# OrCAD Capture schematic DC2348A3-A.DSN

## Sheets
1 PAGE3: size B; title: HIGH POWER POLY-PHASE; rev: 3; company: TM; note: BI-DIRECTIONAL SUPPLY/CHARGER
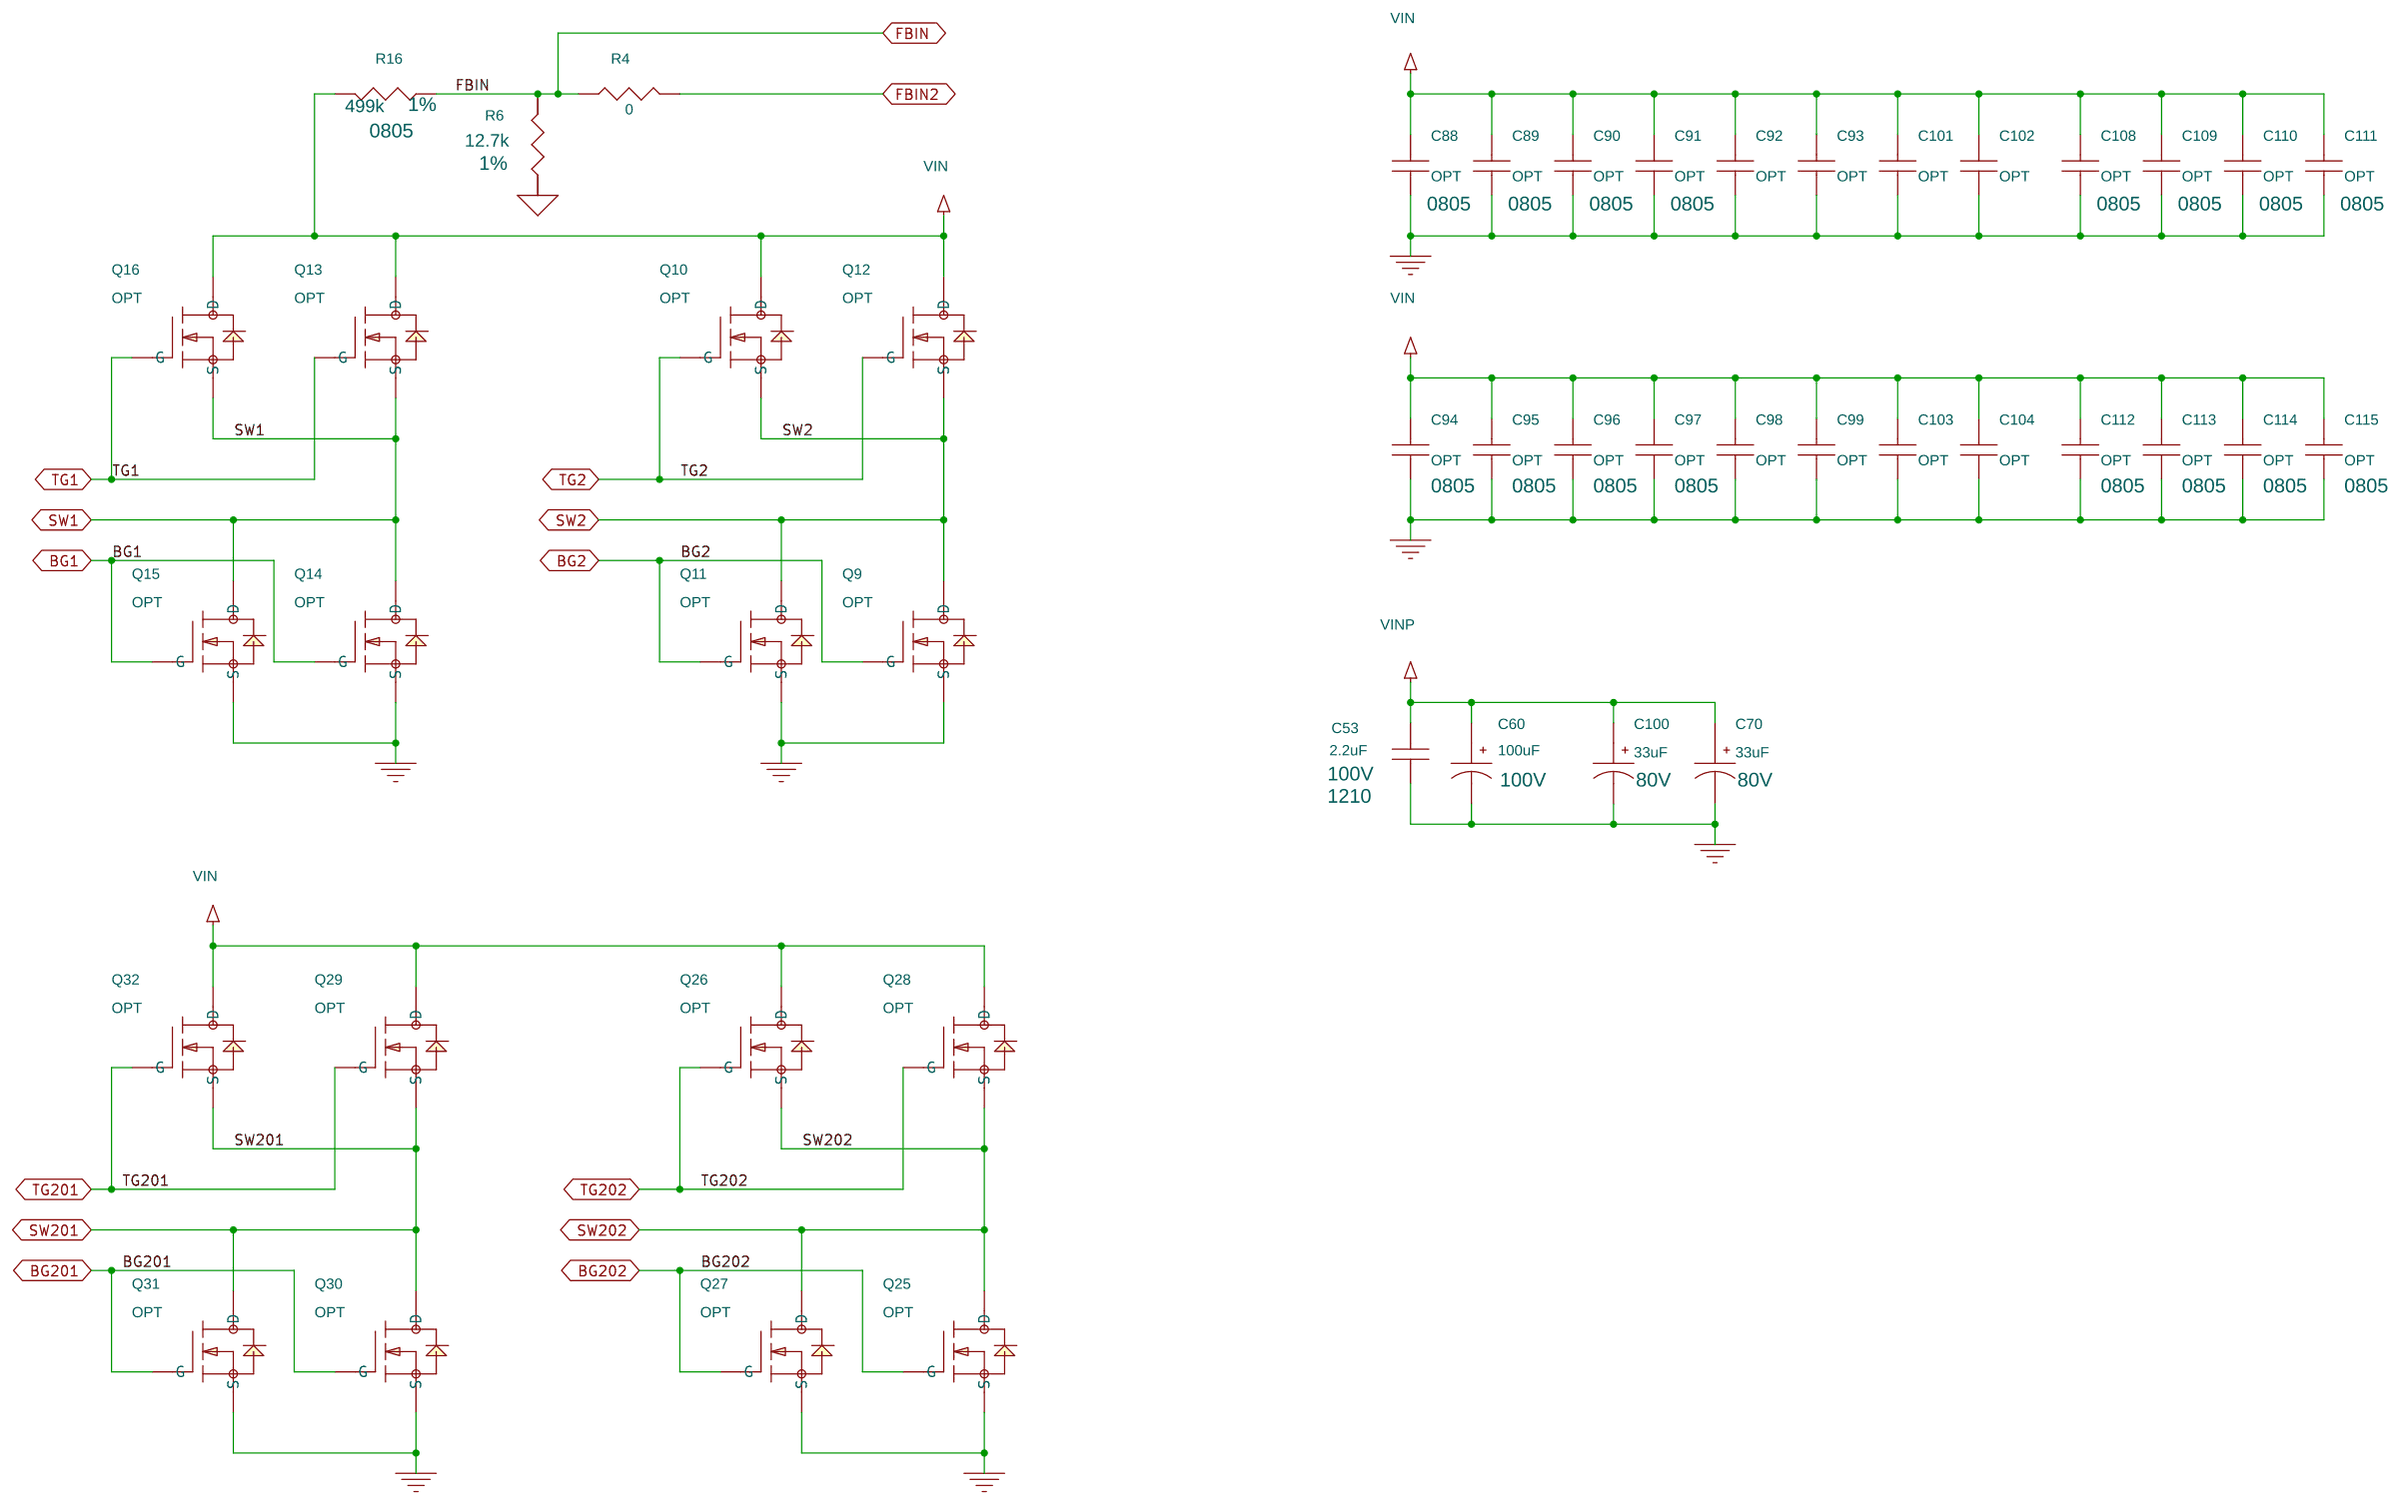
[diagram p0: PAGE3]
2 PAGE1: size Custom
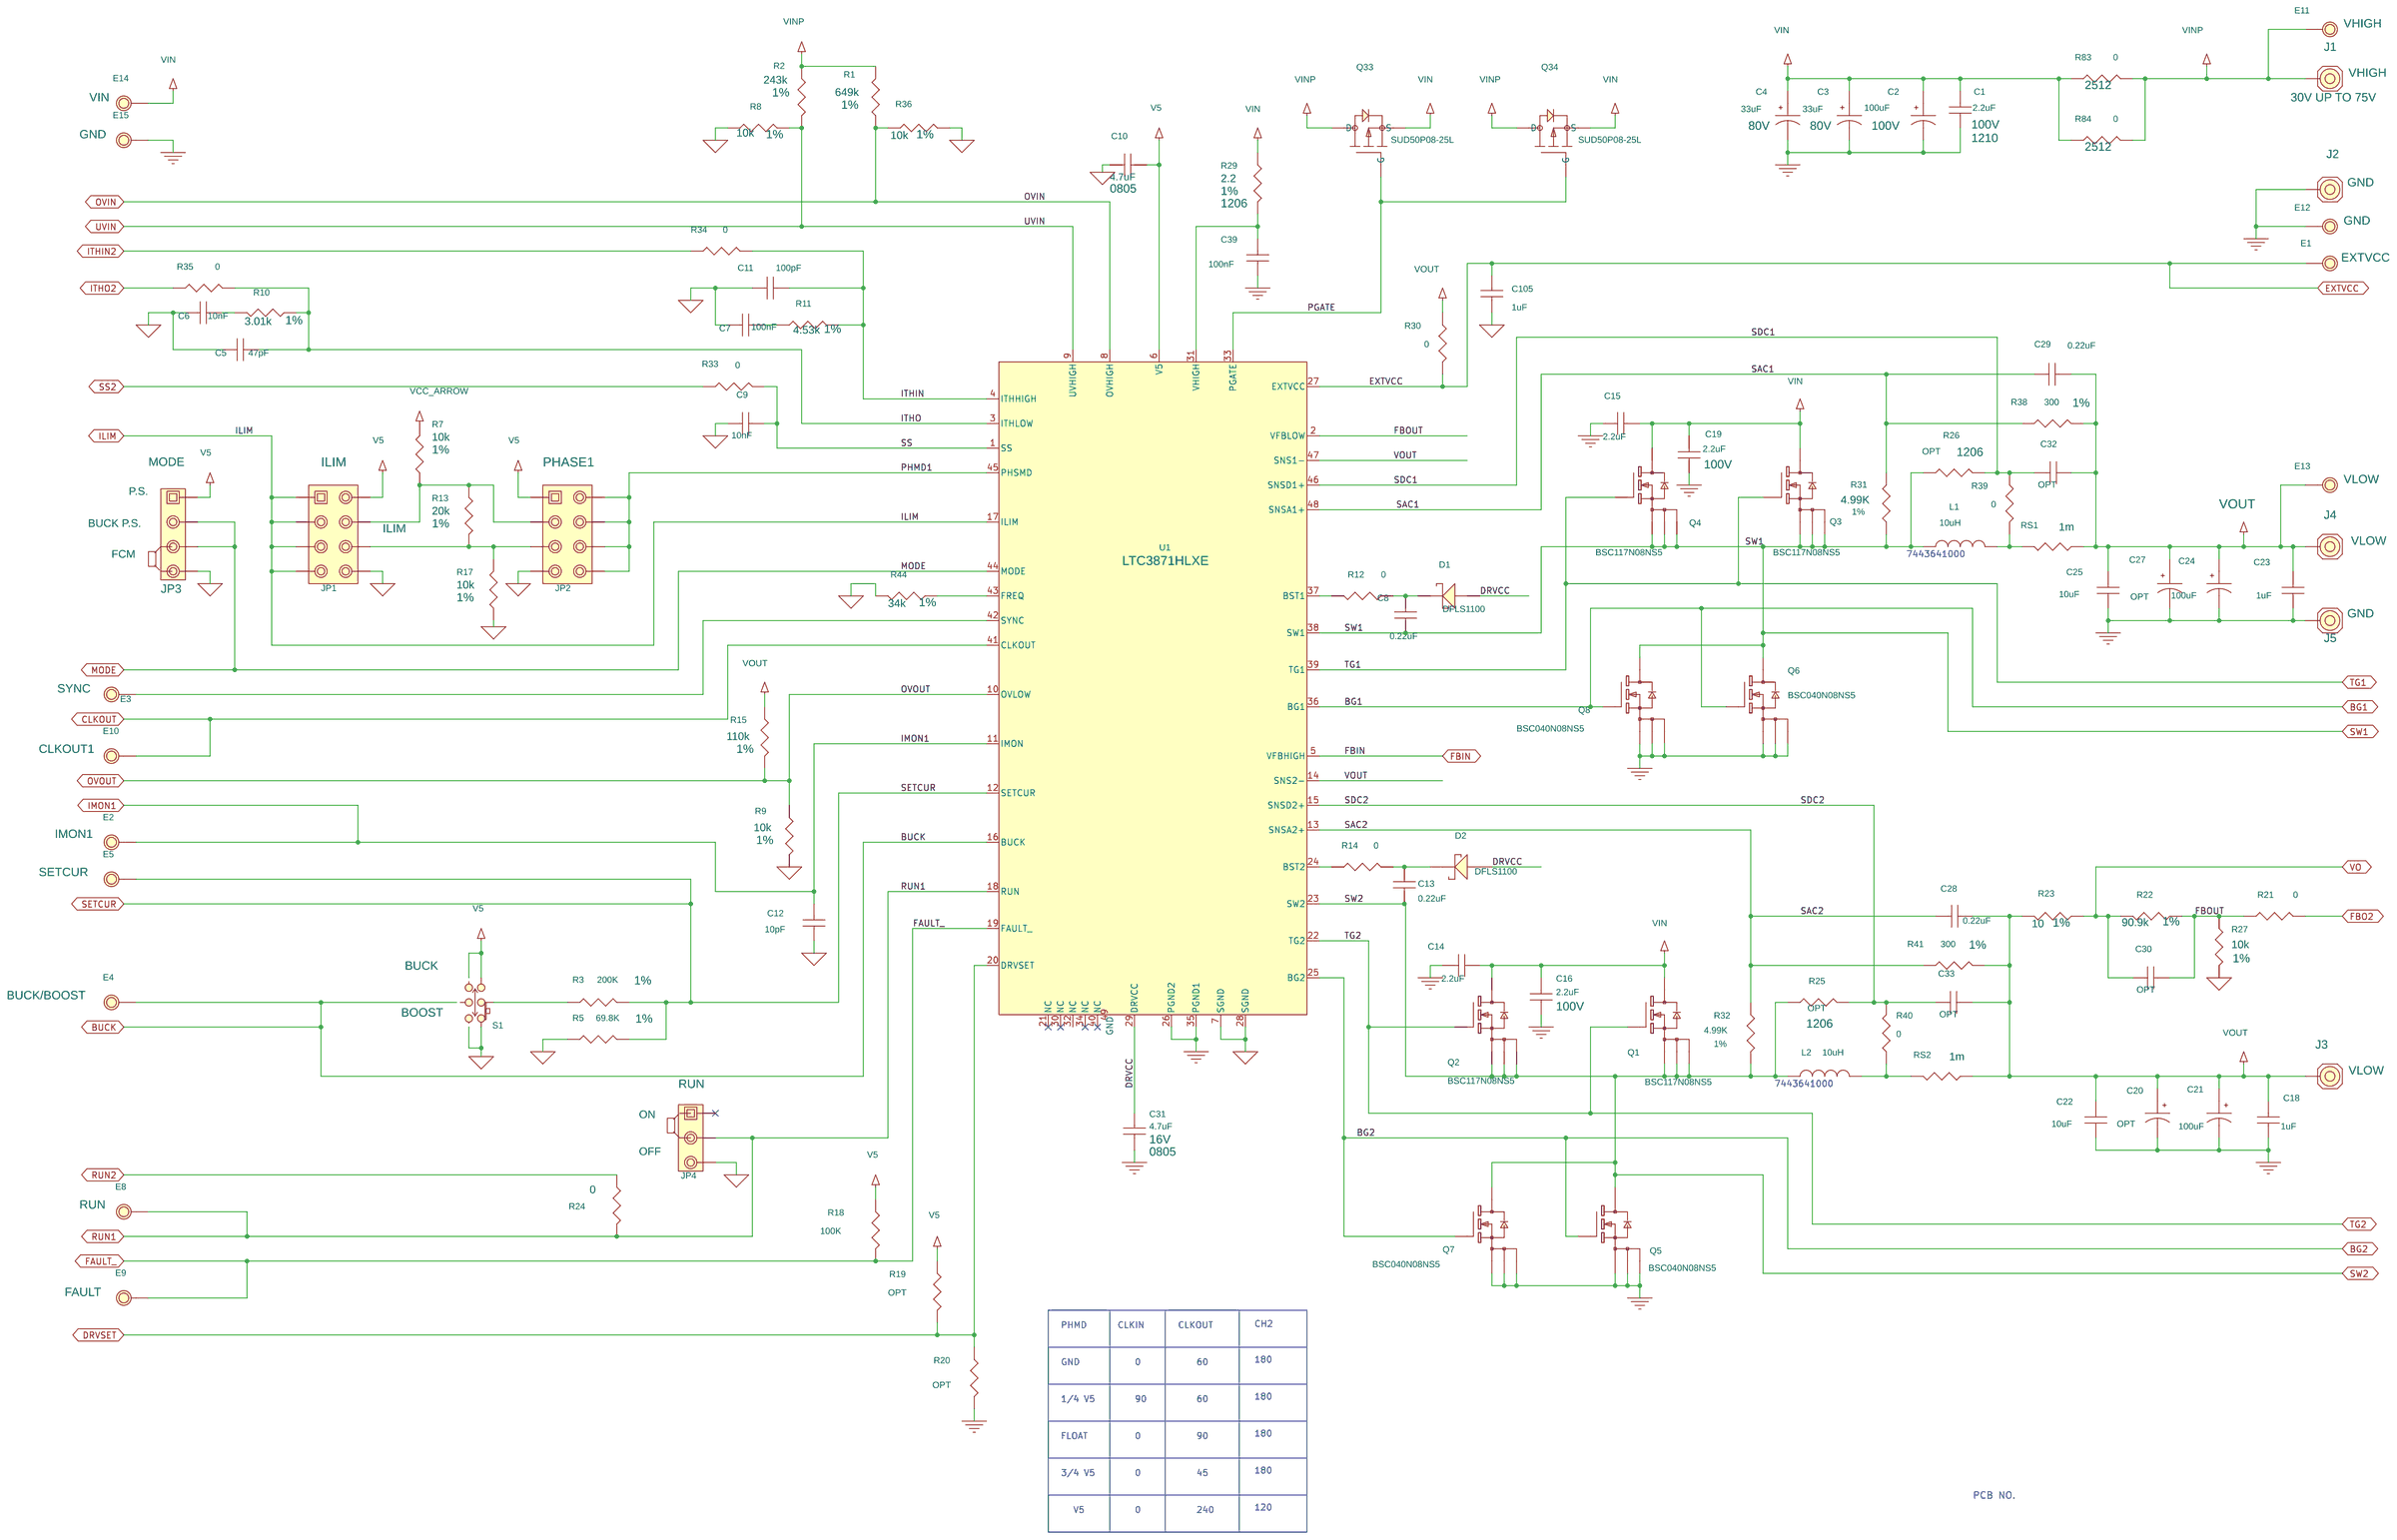
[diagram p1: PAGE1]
3 PAGE2: size Custom
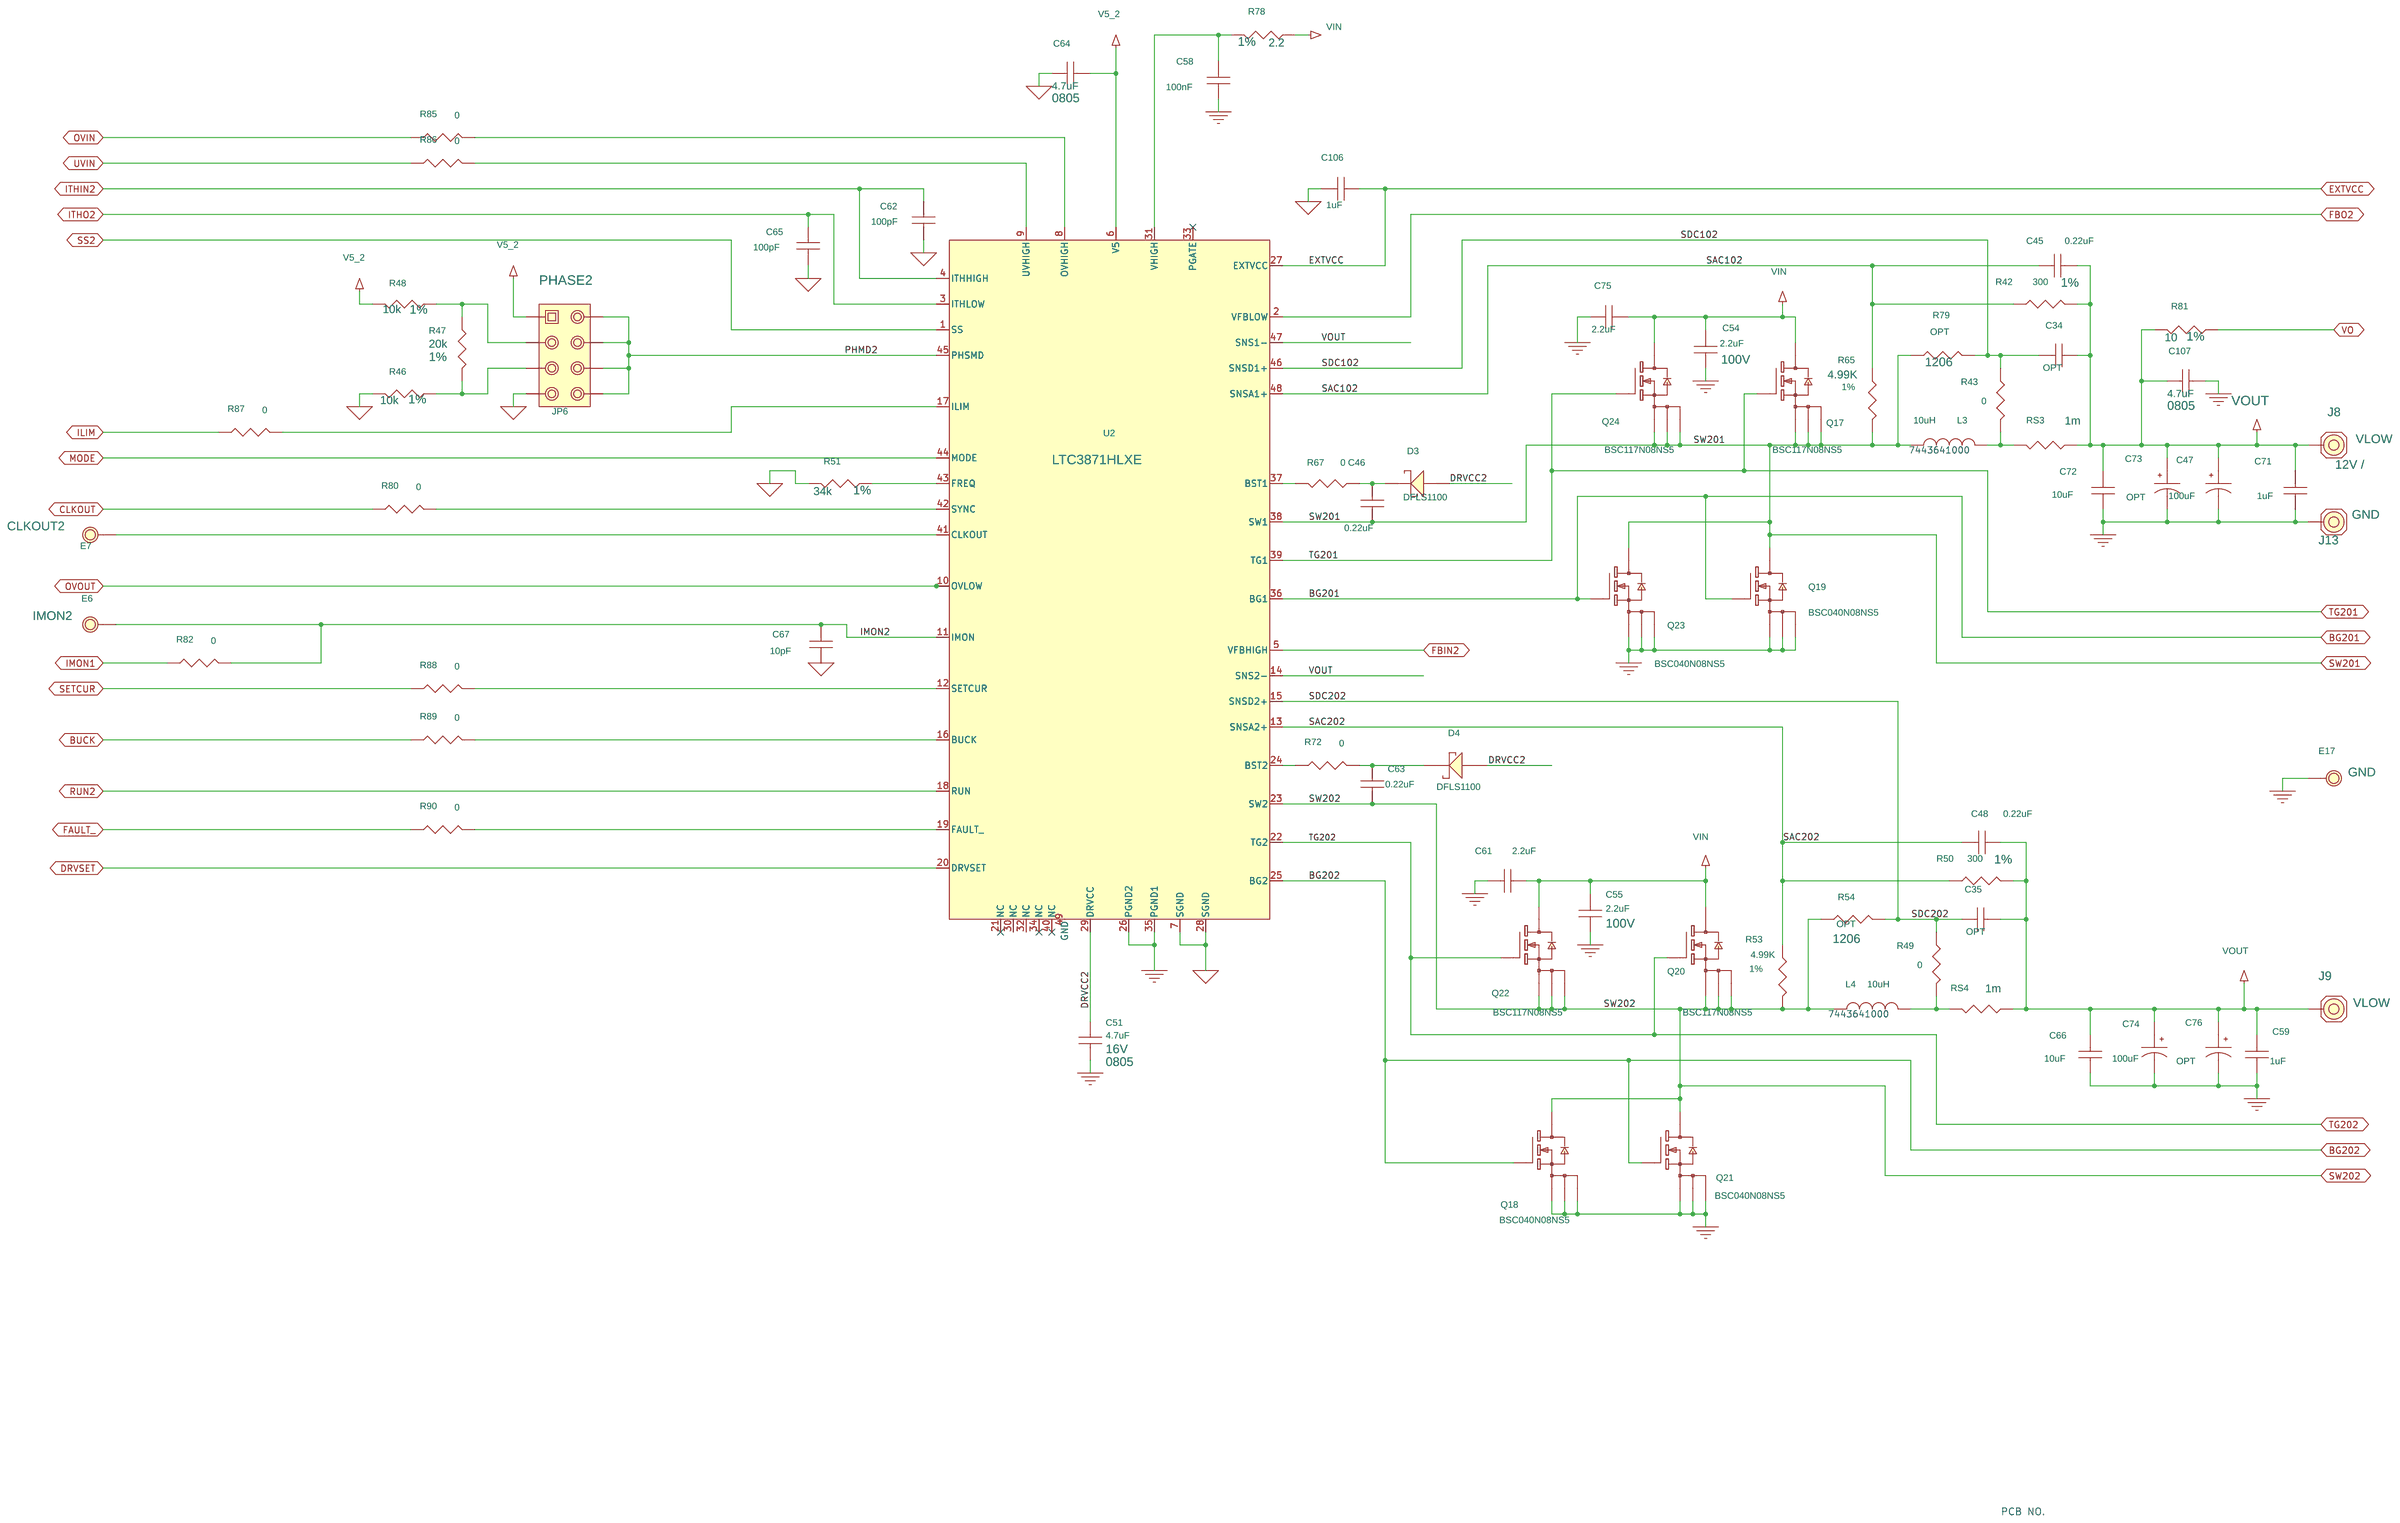
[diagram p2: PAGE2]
4 PAGE4: size A
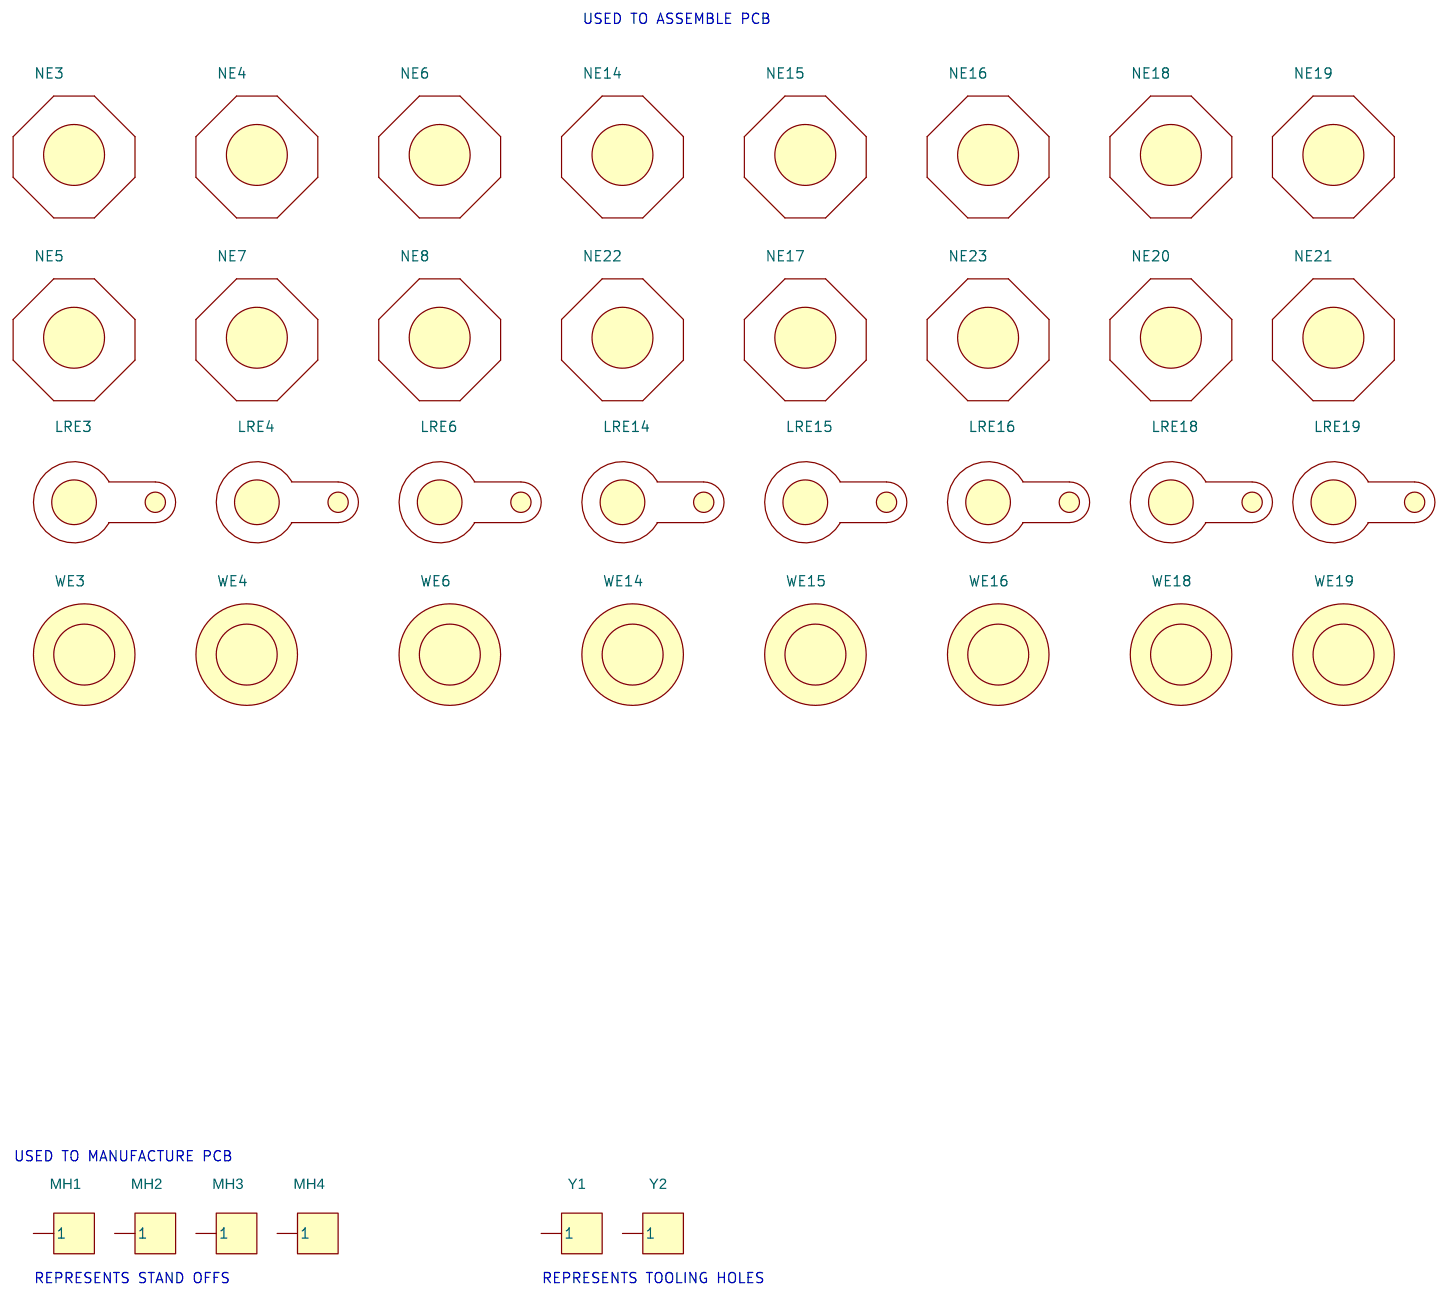
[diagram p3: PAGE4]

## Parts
sheet PAGE1
C1  2.2uF  [1210]
C2  100uF  [CAP\SANYO\CE_16X16.5]
C3  33uF  [CAP\SANYO\8X10.2\CE]
C4  33uF  [CAP\SANYO\8X10.2\CE]
C5  47pF  [0603]
C6  10nF  [0603]
C7  100nF  [0603]
C8  0.22uF  [0603]
C9  10nF  [0603]
C10  4.7uF  [0805]
C11  100pF  [0603]
C12  10pF  [0603]
C13  0.22uF  [0603]
C14  2.2uF  [1210]
C15  2.2uF  [1210]
C16  2.2uF  [1210]
C18  1uF  [0603]
C19  2.2uF  [1210]
C20  OPT  [CAP\SANYO\SVPA_E7]
C21  100uF  [CAP\PANASONIC\6.3X7.7\ZA]
C22  10uF  [1206]
C23  1uF  [0603]
C24  100uF  [CAP\PANASONIC\6.3X7.7\ZA]
C25  10uF  [1206]
C27  OPT  [CAP\SANYO\SVPA_E7]
C28  0.22uF  [0603]
C29  0.22uF  [0603]
C30  OPT  [0603]
C31  4.7uF  [0805]
C32  OPT  [0603]
C33  OPT  [0603]
C39  100nF  [0603]
C105  1uF  [0603]
D1  DFLS1100  [POWERDI_123]
D2  DFLS1100  [POWERDI_123]
E1  EXTVCC  [MM/2501]
E2  IMON1  [MM/2501]
E3  SYNC  [MM/2501]
E4  BUCK/BOOST  [MM/2501]
E5  SETCUR  [MM/2501]
E8  RUN  [MM/2501]
E9  FAULT  [MM/2501]
E10  CLKOUT1  [MM/2501]
E11  VHIGH  [MM/2501]
E12  GND  [MM/2501]
E13  VLOW  [MM/2501]
E14  VIN  [MM/2501]
E15  GND  [MM/2501]
J1  Testpin  [con\lug\10]
J2  Testpin  [con\lug\10]
J3  Testpin  [con\lug\10]
J4  Testpin  [con\lug\10]
J5  Testpin  [con\lug\10]
JP1  2 Pins 2mm Ctrs.  [HDR2X4_2MM]
JP2  2 Pins 2mm Ctrs.  [HDR2X4_2MM]
JP3  3 Pins 2mm Ctrs.  [HDR_1X4_2MM]
JP4  3 Pins 2mm Ctrs.  [commcon2802s03g2]
L1  10uH  [IND\CLCRFT\SER2900]
L2  10uH  [IND\CLCRFT\SER2900]
Q1  BSC117N08NS5  [LFPAK]
Q2  BSC117N08NS5  [LFPAK]
Q3  BSC117N08NS5  [LFPAK]
Q4  BSC117N08NS5  [LFPAK]
Q5  BSC040N08NS5  [LFPAK]
Q6  BSC040N08NS5  [LFPAK]
Q7  BSC040N08NS5  [LFPAK]
Q8  BSC040N08NS5  [LFPAK]
Q33  SUD50P08-25L  [TO252-3]
Q34  SUD50P08-25L  [TO252-3]
R1  649k  [0603]
R2  243k  [0603]
R3  200K  [0603]
R5  69.8K  [0603]
R7  10k  [0603]
R8  10k  [0603]
R9  10k  [0603]
R10  3.01k  [0603]
R11  4.53k  [0603]
R12  0  [0603]
R13  20k  [0603]
R14  0  [0603]
R15  110k  [0603]
R17  10k  [0603]
R18  100K  [0603]
R19  OPT  [0603]
R20  OPT  [0603]
R21  0  [0603]
R22  90.9k  [0603]
R23  10  [0603]
R24  0  [0603]
R25  OPT  [1206]
R26  OPT  [1206]
R27  10k  [0603]
R29  2.2  [1206]
R30  0  [0603]
R31  4.99K  [0603]
R32  4.99K  [0603]
R33  0  [0603]
R34  0  [0603]
R35  0  [0603]
R36  10k  [0603]
R38  300  [0603]
R39  0  [0603]
R40  0  [0603]
R41  300  [0603]
R44  34k  [0603]
R83  0  [2512]
R84  0  [2512]
RS1  1m  [2010]
RS2  1m  [2010]
S1  JP3X1/079\NO\12  [JS202011]
U1  LTC3871HLXE  [LT_LXE-LQFP_7X7]
XJP1  2mm Ctrs.
XJP4  2mm Ctrs.
XJP6  2mm Ctrs.
XJP7  2mm Ctrs.
sheet PAGE2
C34  OPT  [0603]
C35  OPT  [0603]
C45  0.22uF  [0603]
C46  0.22uF  [0603]
C47  100uF  [CAP\PANASONIC\6.3X7.7\ZA]
C48  0.22uF  [0603]
C51  4.7uF  [0805]
C54  2.2uF  [1210]
C55  2.2uF  [1210]
C58  100nF  [0603]
C59  1uF  [0603]
C61  2.2uF  [1210]
C62  100pF  [0603]
C63  0.22uF  [0603]
C64  4.7uF  [0805]
C65  100pF  [0603]
C66  10uF  [1206]
C67  10pF  [0603]
C71  1uF  [0603]
C72  10uF  [1206]
C73  OPT  [CAP\SANYO\SVPA_E7]
C74  100uF  [CAP\PANASONIC\6.3X7.7\ZA]
C75  2.2uF  [1210]
C76  OPT  [CAP\SANYO\SVPA_E7]
C106  1uF  [0603]
C107  4.7uF  [0805]
D3  DFLS1100  [POWERDI_123]
D4  DFLS1100  [POWERDI_123]
E6  IMON2  [MM/2501]
E7  CLKOUT2  [MM/2501]
E17  GND  [MM/2501]
J8  Testpin  [con\lug\10]
J9  Testpin  [con\lug\10]
J13  Testpin  [con\lug\10]
JP6  2 Pins 2mm Ctrs.  [HDR2X4_2MM]
L3  10uH  [IND\CLCRFT\SER2900]
L4  10uH  [IND\CLCRFT\SER2900]
Q17  BSC117N08NS5  [LFPAK]
Q18  BSC040N08NS5  [LFPAK]
Q19  BSC040N08NS5  [LFPAK]
Q20  BSC117N08NS5  [LFPAK]
Q21  BSC040N08NS5  [LFPAK]
Q22  BSC117N08NS5  [LFPAK]
Q23  BSC040N08NS5  [LFPAK]
Q24  BSC117N08NS5  [LFPAK]
R42  300  [0603]
R43  0  [0603]
R46  10k  [0603]
R47  20k  [0603]
R48  10k  [0603]
R49  0  [0603]
R50  300  [0603]
R51  34k  [0603]
R53  4.99K  [0603]
R54  OPT  [1206]
R65  4.99K  [0603]
R67  0  [0603]
R72  0  [0603]
R78  2.2  [1206]
R79  OPT  [1206]
R80  0  [0603]
R81  10  [0603]
R82  0  [0603]
R85  0  [0603]
R86  0  [0603]
R87  0  [0603]
R88  0  [0603]
R89  0  [0603]
R90  0  [0603]
RS3  1m  [2010]
RS4  1m  [2010]
U2  LTC3871HLXE  [LT_LXE-LQFP_7X7]
XJP3  2mm Ctrs.
sheet PAGE3
C53  2.2uF  [1210]
C60  100uF  [CAP\SANYO\CE_16X16.5]
C70  33uF  [CAP\SANYO\8X10.2\CE]
C88  OPT  [0805]
C89  OPT  [0805]
C90  OPT  [0805]
C91  OPT  [0805]
C92  OPT  [0603]
C93  OPT  [0603]
C94  OPT  [0805]
C95  OPT  [0805]
C96  OPT  [0805]
C97  OPT  [0805]
C98  OPT  [0603]
C99  OPT  [0603]
C100  33uF  [CAP\SANYO\8X10.2\CE]
C101  OPT  [0603]
C102  OPT  [0603]
C103  OPT  [0603]
C104  OPT  [0603]
C108  OPT  [0805]
C109  OPT  [0805]
C110  OPT  [0805]
C111  OPT  [0805]
C112  OPT  [0805]
C113  OPT  [0805]
C114  OPT  [0805]
C115  OPT  [0805]
Q9  OPT  [TO252-3]
Q10  OPT  [TO252-3]
Q11  OPT  [TO252-3]
Q12  OPT  [TO252-3]
Q13  OPT  [TO252-3]
Q14  OPT  [TO252-3]
Q15  OPT  [TO252-3]
Q16  OPT  [TO252-3]
Q25  OPT  [TO252-3]
Q26  OPT  [TO252-3]
Q27  OPT  [TO252-3]
Q28  OPT  [TO252-3]
Q29  OPT  [TO252-3]
Q30  OPT  [TO252-3]
Q31  OPT  [TO252-3]
Q32  OPT  [TO252-3]
R4  0  [0603]
R6  12.7k  [0603]
R16  499k  [0805]
sheet PAGE4
LRE3  Lug_Ring
LRE4  Lug_Ring
LRE6  Lug_Ring
LRE14  Lug_Ring
LRE15  Lug_Ring
LRE16  Lug_Ring
LRE18  Lug_Ring
LRE19  Lug_Ring
MH1  CON1  [KEYSTONE_8831]
MH2  CON1  [KEYSTONE_8831]
MH3  CON1  [KEYSTONE_8831]
MH4  CON1  [KEYSTONE_8831]
NE3  NUT
NE4  NUT
NE5  NUT
NE6  NUT
NE7  NUT
NE8  NUT
NE14  NUT
NE15  NUT
NE16  NUT
NE17  NUT
NE18  NUT
NE19  NUT
NE20  NUT
NE21  NUT
NE22  NUT
NE23  NUT
WE3  Washer
WE4  Washer
WE6  Washer
WE14  Washer
WE15  Washer
WE16  Washer
WE18  Washer
WE19  Washer
Y1  CON1  [TOOL\ALGNHL\70]
Y2  CON1  [TOOL\ALGNHL\70]

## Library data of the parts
C1 C14-C16 C19 C53-C55 C61 C75 = CAP_NP_0: CAP, 1210 2.2uF 10% 100V X7R; Part Number: AVX 12101C225KAT2A; VOLTAGE: 100V
C2 C60 = CAP_POL: CAP, 100uF 20% 100V ELEC; Part Number: SUN ELECT. 100CE100KXT; VOLTAGE: 100V
C3 C4 C70 C100 = CAP_POL: CAP, 33uF 20% 80V ELEC; MANUFACTURING: 10TPE330M; Part Number: PANASONIC EEE-FK1K330P; VOLTAGE: 80V
C5 = CAP_NP_0: CAP, 0603 47pF 10% 50V C0G; 1PART: 16V; Part Number: AVX 06035A470KAT2A; VOLTAGE: 50V
C6 = CAP_NP_0: CAP, 0603 10nF 10% 100V X7R; Part Number: AVX 06031C103KAT2A; VOLTAGE: 50V
C7 C39 C58 = CAP_NP_0: CAP, 0603 100nF 10% 50V X7R; Part Number: AVX 06035C104KAT2A; VOLTAGE: 50V
C8 C13 C46 C63 = CAP_NP_0: CAP, 0603 0.22uF 10% 25V X5R; Part Number: AVX 06033D224KAT2A; VOLTAGE: 25V
C9 = CAP_NP_0: CAP, 0603 10nF 10% 100V X7R; 1PART: 16V; Part Number: AVX 06031C103KAT2A; VOLTAGE: 25V
C10 C64 C107 = CAP_NP_0: CAP, 0805 4.7uF 10% 16V X7R; Part Number: AVX 0805YC475KAT2A; VOLTAGE: 16V
C11 C62 C65 = CAP_NP_0: CAP, 0603 100pF 10% 100V NPO; Part Number: AVX 06031A101KAT2A; VOLTAGE: 100V
C12 C67 = CAP_NP_0: CAP, 0603 10pF 10% 100V C0G; Part Number: AVX 06031A100KAT2A / AVX; VOLTAGE: 100V
C18 C23 C59 C71 C105 C106 = CAP_NP_0: CAP, 0603 1uF 10% 25V X7R; Part Number: MURATA GRM188R71E105KA12D; VOLTAGE: 16V
C20 C27 C73 = CAP_POL: CAP, ALUM OPTION; MANUFACTURING: 10TPE330M; Part Number: OPTION; VOLTAGE: 16V
C21 = CAP_POL: CAP, 100uF 20% 25V ALUM; Part Number: PANASONIC EEHZA1E101XP; VOLTAGE: 25V
C22 C25 C66 C72 = CAP_NP_0: CAP, 1206 10uF 10% 25V X7R; Part Number: MURATA GRM31CR71E106KA12L; VOLTAGE: 16V
C24 C74 = CAP_POL: CAP, 100uF 20% 25V ALUM; MANUFACTURING: 10TPE330M; Part Number: PANASONIC EEHZA1E101XP; VOLTAGE: 25V
C28 C29 C45 C48 = CAP_NP_0: CAP, 0603 0.22uF 10% 25V X5R; Part Number: AVX 06033D224KAT2A; VOLTAGE: 16V
C30 = CAP_NP_0: CAP, 0603 OPTION; Part Number: OPTION; VOLTAGE: ( Opt. )
C31 C51 = CAP_NP_0: CAP, 0805 4.7uF 10% 16V X7R; 1PART: 16V; Part Number: AVX 0805YC475KAT2A; VOLTAGE: 16V
C32-C35 = CAP_NP_0: CAP, 0603 OPTION; Part Number: OPTION
D1-D4 = D-SCHOTTKY_0: DIODE, SCHOTTKY, RECTIFIER; Field1: SOD323; Part Number: DIODES INC. DFLS1100-7
E1-E15 E17 = MillMax-2501: TURRET; Part Number: MIIL-MAX 2501-2-00-80-00-00-07-0
J1 = PEM-kfh-032-10: STUD, TESTPIN; 10th Part Field: 30V UP TO 75V; 9th Part Field: VHIGH; Part Number: PEM KFH-032-10
J2 J5 J13 = PEM-kfh-032-10: STUD, TESTPIN; 10th Part Field: 5 - 24V #; 9th Part Field: GND; Part Number: PEM KFH-032-10
J3 J4 J9 = PEM-kfh-032-10: STUD, TESTPIN; 10th Part Field: 12V / 50A; 9th Part Field: VLOW; Part Number: PEM KFH-032-10
JP1 = Samtec_TMM-_0: HEADER, 4PIN, DBL ROW 2mm; 10th Part Field: ILIM; 4th Part Field: BURST; 5th Part Field: FCC; 7th Part Field: SYNC; 9th Part Field: ILIM; Part Number: WURTH 620 008 211 21
JP2 = Samtec_TMM-_0: HEADER, 4PIN, DBL ROW 2mm; 4th Part Field: BURST; 5th Part Field: FCC; 7th Part Field: SYNC; 9th Part Field: PHASE1; Part Number: WURTH 620 008 211 21
JP3 = Samtec_TMM-103-02-L-S_0: HEADER, 4PIN, 2mm; 11th Part Field: BUCK P.S.; 12th Part Field: MODE; 4th Part Field: P.S.; 5th Part Field: ?; 9th Part Field: FCM; Part Number: WURTH 620 004 111 21
JP4 = Samtec_TMM-103-02-L-S: HEADER, 2mm, 3PIN; 11th Part Field: OFF; 12th Part Field: RUN; 9th Part Field: ON; Part Number: WURTH 620 003 111 212
L1 L3 = INDUCTOR: IND, 10uH; Part Number: WURTH 7443641000 / COILCRAFT SER2918H-103; manufacturing: Coilcraft SER1360-802KL
L2 L4 = INDUCTOR: IND, 10uH; Part Number: WURTH 7443641000 / COILCRAFT SER2918H-103; manufacturing: Coilcraft SER1360-472KL
Q1-Q4 Q17 Q20 Q22 Q24 = 2N7002_28: XSTR,  MOSFET N-CH 80V 100A TDSON-8; Part Number: INFINEON BSC117N08NS5
Q5-Q8 Q18 Q19 Q21 Q23 = 2N7002_28: XSTR,  MOSFET N-CH 80V 100A TDSON-8; Part Number: INFINEON BSC040N08NS5
Q33 Q34 = Si2311DS_0: XSTR, SIPMOS, P-CHANNEL; Part Number: VISHAY SUD50P08-25L
R1 = R_1: RES, 0603 649k OHMS 1% 1/10W; %: 1%; Part Number: VISHAY CRCW0603649KFKEA
R2 = R_1: RES, 0603 243k OHMS 1% 1/10W; %: 1%; Part Number: VISHAY CRCW0603243KFKEA
R3 = R_1: RES, 0603 200k OHMS 1% 0.1W; %: 1%; Part Number: VISHAY CRCW0603200KFKEA
R5 = R_1: RES, 0603 69.8k OHMS 1% 0.1W; %: 1%; Part Number: VISHAY CRCW060369K8FKEA
R7-R9 R17 R27 R36 R46 R48 = R_1: RES, 0603 10k OHMS 1% 1/10W; %: 1%; Part Number: VISHAY CRCW060310K0FKEA
R10 = R_1: RES, 0603 3.01k OHMS 1% 1/10W; %: 1%; Part Number: VISHAY CRCW06033K01FKEA
R11 = R_1: RES, 0603 4.53k OHMS 1% 1/10W; %: 1%; Part Number: VISHAY CRCW06034K53FKEA
R12 R14 R34 R67 R72 R80 R82 R85-R90 = R_1: RES, 0603 0 OHM JUMPER; %: 1%; Part Number: VISHAY CRCW06030000Z0EA
R13 R47 = R_1: RES, 0603 20k OHMS 1% 1/10W; %: 1%; Part Number: VISHAY CRCW060320K0FKEA
R15 = R_1: RES, 0603 110k OHMS 1% 1/10W; %: 1%; Part Number: VISHAY CRCW0603110KFKEA
R18 = R_1: RES, 0603 100k OHMS 5% 1/10W; %: 1%; Part Number: VISHAY CRCW0603100KJNEA
R19 = R_1: RES, 0603 OPTION; %: 1%; Part Number: OPTION
R20 = R_1: RES, 0603 OPTION; %: 0.1%; Part Number: OPTION
R4 R21 R24 R30 R33 R35 R39 R40 R43 R49 = R_1: RES, 0603 0 OHM JUMPER; %: 0.1%; Part Number: VISHAY CRCW06030000Z0EA
R22 = R_1: RES, 0603 90.9k OHMS 1% 1/10W; %: 1%; Part Number: VISHAY CRCW060390K9FKEA
R23 R81 = R_1: RES, 0603 10 OHMS 1% 1/10W; %: 1%; Part Number: VISHAY CRCW060310R0FKEA
R25 R26 R54 R79 = R_1: RES, 1206 OPTION; %: 0.1%; Part Number: OPTION
R29 R78 = R_1: RES. 1206 2.2 OHMS 1% 1/4W; %: 1%; Part Number: VISHAY CRCW12062R20FKEA
R31 R32 R53 R65 = R_1: RES, 0603 4.99K OHMS 1% 0.1W; %: 1%; Part Number: VISHAY CRCW06034K99FKEA
R38 R41 R42 R50 = R_1: RES, 0603 300 OHMS 1% 0.1W; %: 1%; Part Number: VISHAY CRCW0603300RFKEA
R44 R51 = R_1: RES, 0603 34k OHMS 1% 0.1W; %: 1%; Part Number: VISHAY CRCW060334K0FKEA
R83 R84 = R_1: RES, 2512 0 OHM JUMPER; %: 0.1%; Part Number: VISHAY CRCW25120000Z0EG
RS1-RS4 = R_1: RES, 2010 0.001 OHM 1% 1W; %: 0.1%; Part Number: VISHAY WSL20101L000FEA18
S1 = JP3X1_079_NO_12_3: SWITCH, SUBMINATURE, SLIDE, SPDT; 1st Part Field: BUCK; 2nd Part Field: BUCK; 3rd Part Field: BOOST; Part Number: C&K-COMPONENTS JS202011CQN
U1 U2 = LTC3890EUFD_79: IC, HIGH POWER BiDIRECTIONAL SUPPLY; Part Number: LINEAR TECH. LTC3871HLXE#PBF
XJP1 XJP3 XJP7 = Samtec_2SN-BK-G_0: SHUNT, 2mm; Part Number: SAMTEC 2SN-BK-G
XJP4 XJP6 = Samtec_2SN-BK-G: SHUNT, 2mm; Part Number: SAMTEC 2SN-BK-G
C47 = CAP_POL: CAP, 100uF 20% 25V ALUM; MANUFACTURING: 10TPE330M; Part Number: PANASONIC EEHZA1E101XP; VOLTAGE: 16V
C76 = CAP_POL: CAP, ALUM OPTION; Part Number: OPTION
J8 = PEM-kfh-032-10: STUD, TESTPIN; 10th Part Field: 12V /; 9th Part Field: VLOW; Part Number: PEM KFH-032-10
JP6 = Samtec_TMM-_0: HEADER, 4PIN, DBL ROW 2mm; 4th Part Field: BURST; 5th Part Field: FCC; 7th Part Field: SYNC; 9th Part Field: PHASE2; Part Number: WURTH 620 008 211 21
C88-C91 C94-C97 C108-C115 = CAP_NP_0: CAP, 0805 OPTION; Part Number: OPTION; VOLTAGE: 50V
C92 C93 C98 C99 C101-C104 = CAP_NP_0: CAP, 0603 OPTION; Part Number: OPTION; VOLTAGE: 50V
Q9-Q16 Q25-Q32 = MOSFET_N-CHANNEL_0: XSTR, MOSFET OPTION; Part Number: INFINEON IPD60N10S4-12 OPTION
R6 = R_1: RES, 0603 12.7k OHMS 1% 1/10W; %: 1%; Part Number: VISHAY CRCW060312K7FKEA
R16 = R_1: RES, 0805 499k OHMS 1% 1/8W; %: 1%; Part Number: VISHAY CRCW0805499KFKEA
LRE3 LRE4 LRE6 LRE14-LRE16 LRE18 LRE19 = Lug_Ring: LUG RING, #10; Part Number: KEYSTONE 8205
MH1-MH4 = CON1: STANDOFF, SNAP ON; Part Number: KEYSTONE 8834
NE3-NE8 NE14-NE23 = NUT: NUT, BRASS 10-32; Part Number: ANY #10-32
WE3 WE4 WE6 WE14-WE16 WE18 WE19 = Washer: WASHER, #10 TIN PLATED BRASS; Part Number: ANY #10 EXT BZ TN
Y1 Y2 = CON1: DO NOT STUFF; Part Number: PADS ONLY

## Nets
GND: C1.1 C2.2 C3.2 C4.2 C14.2 C15.1 C16.1 C18.1 C19.1 C20.2 C21.2 C22.1 C23.1 C24.2 C25.1 C27.2 C31.2 C39.1 C47.2 C51.2 C53.1 C54.1 C55.1 C58.1 C59.1 C60.2 C61.2 C66.1 C70.2 C71.1 C72.1 C73.2 C74.2 C75.1 C76.2 C88.1 C89.1 C90.1 C91.1 C92.1 C93.1 C94.1 C95.1 C96.1 C97.1 C98.1 C99.1 C100.2 C101.1 C102.1 C103.1 C104.1 C107.2 C108.1 C109.1 C110.1 C111.1 C112.1 C113.1 C114.1 C115.1 E12.1 E15.1 E17.1 J2.1 J5.1 J13.1 Q5.1 Q5.2 Q5.3 Q6.1 Q6.2 Q6.3 Q7.1 Q7.2 Q7.3 Q8.1 Q8.2 Q8.3 Q9.3(S) Q11.3(S) Q14.3(S) Q15.3(S) Q18.1 Q18.2 Q18.3 Q19.1 Q19.2 Q19.3 Q21.1 Q21.2 Q21.3 Q23.1 Q23.2 Q23.3 Q25.3(S) Q27.3(S) Q30.3(S) Q31.3(S) R20.1 U1.26(PGND2) U1.35(PGND1) U1.49(GND) U2.26(PGND2) U2.35(PGND1) U2.49(GND)
GNDSIGNAL: C5.1 C6.1 C7.1 C9.1 C10.1 C11.1 C12.1 C62.2 C64.1 C65.2 C67.1 C105.2 C106.2 JP1.8 JP2.7 JP3.4 JP4.3 JP6.7 R5.1 R6.1 R8.1 R9.1 R17.1 R27.1 R36.1 R44.2 R46.2 R51.2 S1.3 S1.6 U1.7(SGND) U1.28(SGND) U2.7(SGND) U2.28(SGND)
V5: C10.2 JP1.2 JP2.1 JP3.1 R7.2 R18.2 R19.2 S1.1 S1.4 U1.6(V5)
V5_2: C64.2 JP6.1 R48.2 U2.6(V5)
VIN: C1.2 C2.1 C3.1 C4.1 C14.1 C15.2 C16.2 C19.2 C54.2 C55.2 C61.1 C75.2 C88.2 C89.2 C90.2 C91.2 C92.2 C93.2 C94.2 C95.2 C96.2 C97.2 C98.2 C99.2 C101.2 C102.2 C103.2 C104.2 C108.2 C109.2 C110.2 C111.2 C112.2 C113.2 C114.2 C115.2 E14.1 Q1.5 Q2.5 Q3.5 Q4.5 Q10.2(D) Q12.2(D) Q13.2(D) Q16.2(D) Q17.5 Q20.5 Q22.5 Q24.5 Q26.2(D) Q28.2(D) Q29.2(D) Q32.2(D) Q33.3(S) Q34.3(S) R16.2 R29.2 R78.2 R83.1 R84.1
VINP: C53.2 C60.1 C70.1 C100.1 E11.1 J1.1 Q33.2(D) Q34.2(D) R1.1 R2.2 R83.2 R84.2
BG1: Q6.4 Q8.4 Q14.1(G) Q15.1(G) U1.36(BG1)
BG2: Q5.4 Q7.4 Q9.1(G) Q11.1(G) U1.25(BG2)
BG201: Q19.4 Q23.4 Q30.1(G) Q31.1(G) U2.36(BG1)
BG202: Q18.4 Q21.4 Q25.1(G) Q27.1(G) U2.25(BG2)
BUCK: E4.1 R89.1 S1.5 U1.16(BUCK)
CLKOUT: E10.1 R80.1 U1.41(CLKOUT)
DRVCC: C31.1 D1.2 D2.2 U1.29(DRVCC)
DRVCC2: C51.1 D3.2 D4.2 U2.29(DRVCC)
DRVSET: R19.1 R20.2 U1.20(DRVSET) U2.20(DRVSET)
EXTVCC: C105.1 C106.1 E1.1 R30.1 U1.27(EXTVCC) U2.27(EXTVCC)
FAULT_: E9.1 R18.1 R90.1 U1.19(FAULT_)
FBIN: R4.2 R6.2 R16.1 U1.5(VFBHIGH)
FBIN2: R4.1 U2.5(VFBHIGH)
FBO2: R21.1 U2.2(VFBLOW)
FBOUT: C30.2 R21.2 R22.1 R27.2 U1.2(VFBLOW)
ILIM: JP1.1 JP1.3 JP1.5 JP1.7 R87.1 U1.17(ILIM)
IMON1: C12.2 E2.1 R82.1 U1.11(IMON)
IMON2: C67.2 E6.1 R82.2 U2.11(IMON)
ITHIN: C11.2 R11.1 R34.2 U1.4(ITHHIGH)
ITHIN2: C62.1 R34.1 U2.4(ITHHIGH)
ITHO: C5.2 R10.1 R35.2 U1.3(ITHLOW)
ITHO2: C65.1 R35.1 U2.3(ITHLOW)
MODE: JP3.2 JP3.3 U1.44(MODE) U2.44(MODE)
OVIN: R1.2 R36.2 R85.1 U1.8(OVHIGH)
OVOUT: R9.2 R15.1 U1.10(OVLOW) U2.10(OVLOW)
PGATE: Q33.1(G) Q34.1(G) U1.33(PGATE)
PHMD1: JP2.2 JP2.4 JP2.6 JP2.8 U1.45(PHSMD)
PHMD2: JP6.2 JP6.4 JP6.6 JP6.8 U2.45(PHSMD)
RUN1: E8.1 JP4.2 R24.1 U1.18(RUN)
RUN2: R24.2 U2.18(RUN)
SAC1: C29.1 R31.2 R38.2 U1.48(SNSA1+)
SAC2: C28.2 R32.1 R41.1 U1.13(SNSA2+)
SAC102: C45.1 R42.2 R65.2 U2.48(SNSA1+)
SAC202: C48.2 R50.1 R53.1 U2.13(SNSA2+)
SDC1: C32.2 R26.1 R39.2 U1.46(SNSD1+)
SDC2: C33.1 R25.2 R40.2 U1.15(SNSD2+)
SDC102: C34.2 R43.2 R79.1 U2.46(SNSD1+)
SDC202: C35.1 R49.2 R54.2 U2.15(SNSD2+)
SETCUR: E5.1 R3.2 R5.2 R88.1 U1.12(SETCUR)
SS: C9.2 R33.2 U1.1(SS)
SS2: R33.1 U2.1(SS)
SW1: C8.1 L1.1 Q3.1 Q3.2 Q3.3 Q4.1 Q4.2 Q4.3 Q6.5 Q8.5 Q13.3(S) Q14.2(D) Q15.2(D) Q16.3(S) R26.2 R31.1 U1.38(SW1)
SW2: C13.2 L2.2 Q1.1 Q1.2 Q1.3 Q2.1 Q2.2 Q2.3 Q5.5 Q7.5 Q9.2(D) Q10.3(S) Q11.2(D) Q12.3(S) R25.1 R32.2 U1.23(SW2)
SW201: C46.1 L3.1 Q17.1 Q17.2 Q17.3 Q19.5 Q23.5 Q24.1 Q24.2 Q24.3 Q29.3(S) Q30.2(D) Q31.2(D) Q32.3(S) R65.1 R79.2 U2.38(SW1)
SW202: C63.2 L4.2 Q18.5 Q20.1 Q20.2 Q20.3 Q21.5 Q22.1 Q22.2 Q22.3 Q25.2(D) Q26.3(S) Q27.2(D) Q28.3(S) R53.2 R54.1 U2.23(SW2)
TG1: Q3.4 Q4.4 Q13.1(G) Q16.1(G) U1.39(TG1)
TG2: Q1.4 Q2.4 Q10.1(G) Q12.1(G) U1.22(TG2)
TG201: Q17.4 Q24.4 Q29.1(G) Q32.1(G) U2.39(TG1)
TG202: Q20.4 Q22.4 Q26.1(G) Q28.1(G) U2.22(TG2)
UVIN: R2.1 R8.2 R86.1 U1.9(UVHIGH)
VO: C30.1 R22.2 R23.1 R81.1
VOUT: C18.2 C20.1 C21.1 C22.2 C23.2 C24.1 C25.2 C27.1 C28.1 C29.2 C32.1 C33.2 C34.1 C35.2 C45.2 C47.1 C48.1 C59.2 C66.2 C71.2 C72.2 C73.1 C74.1 C76.1 C107.1 E13.1 J3.1 J4.1 J8.1 J9.1 R15.2 R23.2 R30.2 R38.1 R41.2 R42.1 R50.2 R81.2 RS1.1 RS2.2 RS3.2 RS4.1 U1.14(SNS2-) U1.47(SNS1-) U2.14(SNS2-) U2.47(SNS1-)
N16723613: C39.2 R29.1 U1.31(VHIGH)
N17352805: L1.2 R39.1 RS1.2
N19612564: L2.1 R40.1 RS2.1
N19638427: C7.2 R11.2
N19643876: C6.2 R10.2
N19689499: JP1.6 JP2.5 R13.1 R17.2
N19693977: JP1.4 JP2.3 R7.1 R13.2
N19716351: R44.1 U1.43(FREQ)
N19723679: E3.1 U1.42(SYNC)
N19757610: C58.2 R78.1 U2.31(VHIGH)
N19757715: L3.2 R43.1 RS3.1
N19757716: L4.1 R49.1 RS4.2
N19757838: R72.1 U2.24(BST2)
N19757840: C63.1 D4.1 R72.2
N19757867: R90.2 U2.19(FAULT_)
N19757954: R51.1 U2.43(FREQ)
N19757958: E7.1 U2.41(CLKOUT)
N19757976: R89.2 U2.16(BUCK)
N20600260: R88.2 U2.12(SETCUR)
N21281486: R87.2 U2.17(ILIM)
N21636897: JP6.5 R46.1 R47.1
N21640785: JP6.3 R47.2 R48.1
N21947054: R86.2 U2.9(UVHIGH)
N21947071: R85.2 U2.8(OVHIGH)
N21972963: R14.1 U1.24(BST2)
N22013700: C8.2 D1.1 R12.2
N22013776: R12.1 U1.37(BST1)
N22019659: C13.1 D2.1 R14.2
N22044941: R67.1 U2.37(BST1)
N22044944: C46.2 D3.1 R67.2
N22072121: R80.2 U2.42(SYNC)
N22085902: R3.1 S1.2

Not connected (* = marked no-connect by the designer): JP4 1*; MH1 1; MH2 1; MH3 1; MH4 1; U1 21(NC)* 30(NC)* 32(NC) 34(NC)* 40(NC)*; U2 21(NC)* 30(NC) 32(NC) 33(PGATE)* 34(NC)* 40(NC)*; Y1 1; Y2 1

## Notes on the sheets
sheet 2
- 7443641000
- 7443641000
- PHMD
- CLKIN
- CLKOUT
- CH2
- GND
- 0
- 60
- 180
- 1/4 V5
- 90
- 60
- 180
- FLOAT
- 0
- 90
- 180
- 3/4 V5
- 0
- 45
- 180
- PCB NO.
- V5
- 0
- 240
- 120
sheet 3
- 7443641000
- 7443641000
- PCB NO.
sheet 4
- USED TO ASSEMBLE PCB
- USED TO MANUFACTURE PCB
- REPRESENTS STAND OFFS
- REPRESENTS TOOLING HOLES
